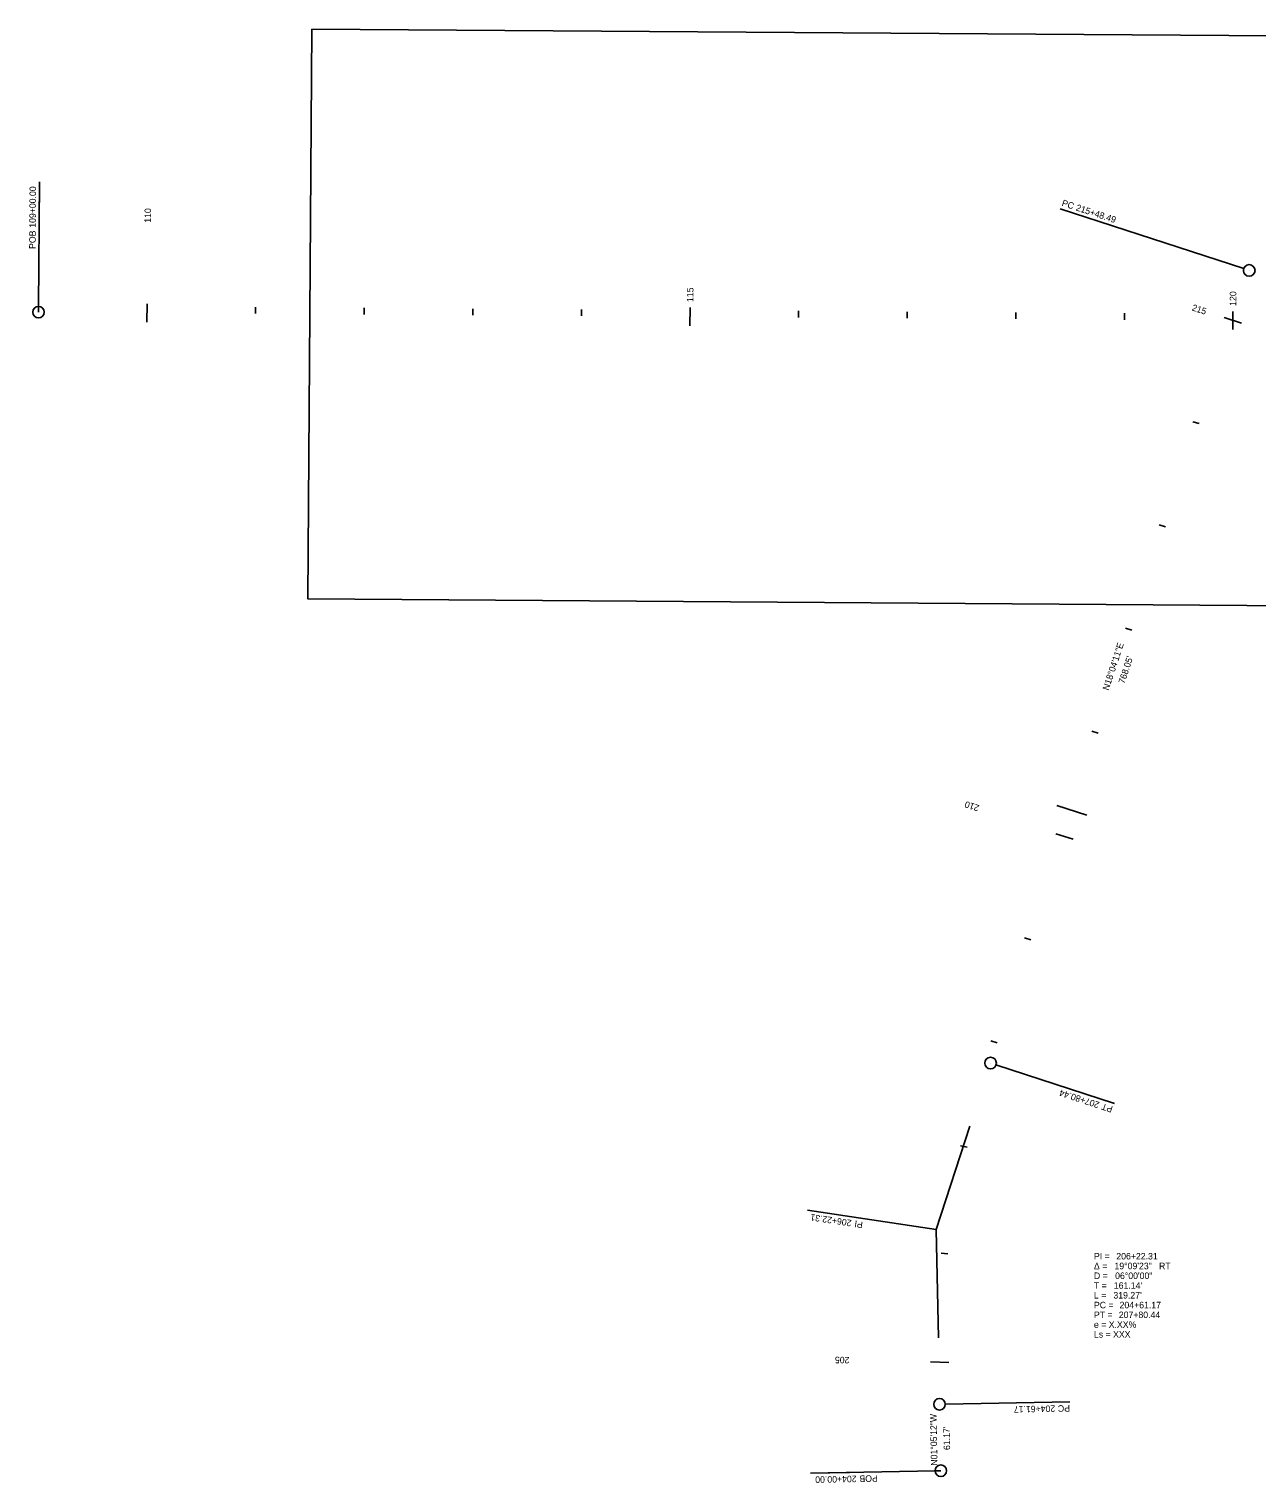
# Model space of a CAD drawing. Extents: x 1802364 to 1804577, y 572742 to 575010.
# Drawn here: x 1802364 to 1803494, y 572742 to 574081 of the extents above; entities that cross this region are included whole.
import ezdxf

# ---------------------------------------------------------------- set-up
doc = ezdxf.new("R2010")
doc.units = 0
for name, color, linetype in [('_CIVIL_CONSTRUCTION', 7, 'Continuous'), ('MOD_CMP_ACHM Leveling', 7, 'Continuous'), ('MOD_COR', 7, 'Continuous'), ('MOD_COR_TemplateDrop', 7, 'Continuous')]:
    doc.layers.add(name, color=color, linetype=linetype)

msp = doc.modelspace()

# ---------------------------------------------------------------- linework, layer by layer
at = {"layer": '_CIVIL_CONSTRUCTION'}
for p, q in [((1802372.2, 573825.3), (1802373, 573940)), ((1802373, 573940), (1802372.8, 573904)), ((1803482.1, 573860.1), (1803313.2, 573915.2)), ((1803313.2, 573915.2), (1803313.2, 573915.2)), ((1803487.2, 573858.4), (1803487.2, 573858.4)), ((1802372.2, 573826), (1802372.2, 573820)), ((1802372.2, 573820), (1802372.2, 573820)), ((1802472.2, 573827.7), (1802472.1, 573810.9)), ((1802572.2, 573824.6), (1802572.2, 573818.6)), ((1802672.2, 573823.9), (1802672.2, 573817.9)), ((1802772.2, 573823.2), (1802772.2, 573817.2)), ((1802872.2, 573822.5), (1802872.2, 573816.5)), ((1802972.2, 573824.2), (1802972.1, 573807.4)), ((1803072.2, 573821.1), (1803072.2, 573815.1)), ((1803172.2, 573820.4), (1803172.2, 573814.4)), ((1803272.2, 573819.7), (1803272.2, 573813.7)), ((1803372.2, 573819), (1803372.2, 573813)), ((1803472.2, 573820.7), (1803472.1, 573803.9)), ((1803464.2, 573815), (1803480.1, 573809.7)), ((1803435.4, 573719.1), (1803441.1, 573717.3)), ((1803404.4, 573624.1), (1803410.1, 573622.2)), ((1803373.4, 573529), (1803379.1, 573527.1)), ((1803342.4, 573433.9), (1803348.1, 573432.1)), ((1803309.1, 573339.6), (1803325, 573334.4)), ((1803280.3, 573243.8), (1803286, 573241.9)), ((1803249.3, 573148.7), (1803255, 573146.9)), ((1803249, 573128.3), (1803249, 573128.3)), ((1803254, 573126.6), (1803363, 573091.1)), ((1803363, 573091.1), (1803363, 573091.1)), ((1803199, 572975.1), (1803230, 573070.2)), ((1803221.4, 573052.2), (1803227.3, 573050.8)), ((1803199, 572975.1), (1803080.3, 572992.8)), ((1803080.3, 572992.8), (1803080.3, 572992.8)), ((1803199, 572975.1), (1803200.9, 572875.1)), ((1803203.5, 572953.2), (1803209.5, 572952.5)), ((1803193.7, 572853), (1803210.5, 572852.6)), ((1803202, 572814), (1803202, 572814)), ((1803207.4, 572814.1), (1803322, 572816.3)), ((1803322, 572816.3), (1803322, 572816.3)), ((1803197.9, 572752.7), (1803083.2, 572750.5)), ((1803083.2, 572750.5), (1803119.2, 572751.2)), ((1803197.2, 572752.7), (1803203.2, 572752.8)), ((1803203.2, 572752.8), (1803203.2, 572752.8))]:
    msp.add_line(p, q, dxfattribs=at)
for centre in [(1803487.2, 573858.4), (1802372.2, 573820), (1803249, 573128.3), (1803202, 572814), (1803203.2, 572752.8)]:
    msp.add_circle(centre, 5.34, dxfattribs=at)
at = {"layer": 'MOD_CMP_ACHM Leveling'}
msp.add_line((1803337.8, 573356.6), (1803310.1, 573365.6), dxfattribs=at)
at = {"layer": 'MOD_COR'}
msp.add_lwpolyline([(1802624, 574080.7), (1802620.3, 573555.8), (1804220.3, 573544.6), (1804224, 574069.6)], close=True, dxfattribs=at)

# ---------------------------------------------------------------- texts
at = {"layer": '_CIVIL_CONSTRUCTION'}
for s, rotation, p in [('109+00.00', 89.6021, (1802369.7, 573897.7)), ('PC', 341.9303, (1803314.1, 573918.1)), ('110', 89.6021, (1802475.8, 573902.3)), ('215+48.49', 341.9303, (1803327.1, 573913.8)), ('POB ', 89.6021, (1802369.6, 573878.2)), ('115', 89.6021, (1802975.3, 573829.3)), ('120', 89.6021, (1803475.2, 573825.8)), ('215', 341.9303, (1803433.9, 573821.7)), ('N18°04\'11"E', 71.9303, (1803357.7, 573471.1)), ('210', 161.9303, (1803239.1, 573365.6)), ('207+80.44', 161.9303, (1803349.8, 573092.2)), ('PT', 161.9303, (1803362.1, 573088.2)), ('206+22.31', 171.5085, (1803121.3, 572983.7)), ('PI ', 171.5085, (1803131.7, 572982.1)), ('205', 178.757, (1803119.1, 572857.6)), ('204+61.17', 181.0867, (1803308.5, 572813)), ('PC', 181.0867, (1803322.1, 572813.3)), ('N01°05\'12"W', 91.0867, (1803200.1, 572757.5)), ('204+00.00', 181.0867, (1803125.6, 572748.3)), ('POB ', 181.0867, (1803145.1, 572748.7))]:
    msp.add_text(s, height=6, rotation=rotation, dxfattribs=at).set_placement(p)
for s, p in [('PI = ', (1803344.2, 572947.4)), ('206+22.31', (1803364.8, 572947.4)), ('Δ = ', (1803344.2, 572938.4)), ('D = ', (1803344.2, 572929.4)), ('19°09\'23"', (1803363.1, 572938.4)), ('06°00\'00"', (1803363.7, 572929.4)), (' RT', (1803401.9, 572938.4)), ('T = ', (1803344.2, 572920.4)), ("161.14'", (1803362.5, 572920.4)), ('L = ', (1803344.2, 572911.4)), ('PC = ', (1803344.2, 572902.4)), ("319.27'", (1803362.1, 572911.4)), ('204+61.17', (1803367.8, 572902.4)), ('PT = ', (1803344.2, 572893.4)), ('207+80.44', (1803367.1, 572893.4)), ('e = X.XX%', (1803344.2, 572884.4)), ('Ls = XXX', (1803344.2, 572875.4))]:
    msp.add_text(s, height=6, dxfattribs=at).set_placement(p)
at = {"layer": 'MOD_COR_TemplateDrop'}
for s, rotation, p in [("768.05'", 71.9303, (1803372.3, 573477.2)), ("61.17'", 91.0867, (1803211.8, 572771.9))]:
    msp.add_text(s, height=6, rotation=rotation, dxfattribs=at).set_placement(p)

doc.saveas('drawing.dxf')
